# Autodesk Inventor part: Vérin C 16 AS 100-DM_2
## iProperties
Shininess: 20.0
Angle Display Precision: 2
Document Length Units: 11269
Document Angle Units: 11279
Document Time Units: 11290
Document Mass Units: 11283
Document Length Units Precision: 3
Document Angle Units Precision: 2
Created: 2002-02
Part Number: Vérin C 16 AS 100-DM_2
Material: Par défaut
Document SubType Name: Modélisation
Designer: Administrateur
Density: 0.0
Volumn: 0.0
Area: 0.0
PropertySet Name: Model Information
Control State: 0
Master: False
Checked Out: False
Author: Administrateur
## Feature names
1. Base1
